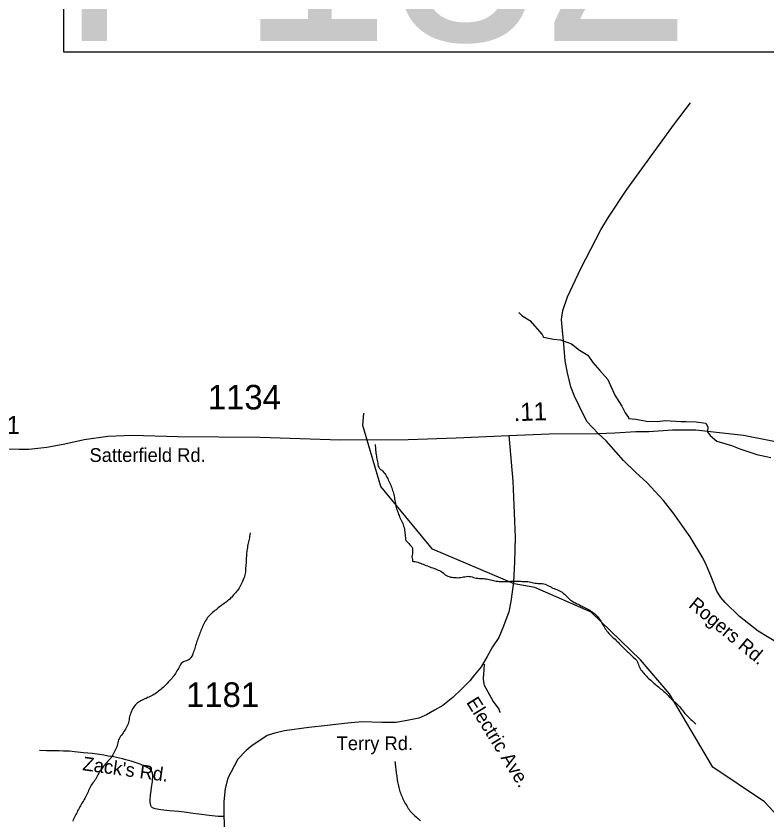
# Model space of a CAD drawing. Extents: x 1950930 to 2061844, y 904556 to 1017002.
# Drawn here: x 1990305 to 1995505, y 917098 to 922665 of the extents above; entities that cross this region are included whole.
import ezdxf

# ---------------------------------------------------------------- set-up
doc = ezdxf.new("R2010")
doc.units = 0
for name, color, linetype in [('Exist Hydrographic Creek Single Shore', 7, 'Continuous'), ('Exist Hydrographic Misc Water Feature', 7, 'Continuous'), ('Exist Road Non-System Type 51', 7, 'Continuous'), ('Exist Road Non-System Type 51 Label', 7, 'Continuous'), ('Exist Road Primary US Structure Standard Bridge CELL', 7, 'Continuous'), ('Exist Road Secondary Structure Pipe Number Label', 7, 'Continuous'), ('Exist Road Secondary Type 41 Attributed', 7, 'Continuous'), ('Exist Road Secondary Type 51 Attributed', 7, 'Continuous'), ('Exist Road Secondary Type 51 Label', 7, 'Continuous'), ('Exist Road Secondary Type 51 Number Label', 7, 'Continuous')]:
    doc.layers.add(name, color=color, linetype=linetype)

msp = doc.modelspace()

# ---------------------------------------------------------------- linework, layer by layer
at = {"layer": 'Exist Hydrographic Creek Single Shore'}
msp.add_lwpolyline([(1992928.9, 917501.3), (1992930.3, 917491.4), (1992931.1, 917481.6), (1992932.4, 917470.8), (1992932.8, 917460.9), (1992934.2, 917451), (1992935, 917441.2), (1992936.5, 917431.2), (1992938.1, 917421.2), (1992939.5, 917411.6), (1992940.8, 917401.7), (1992942.6, 917391.7), (1992943.8, 917381.8), (1992945.3, 917372.3), (1992946.9, 917362.2), (1992948.4, 917352.3), (1992950.4, 917342.2), (1992952.3, 917332.6), (1992954.9, 917322.4), (1992957, 917312.8), (1992960.3, 917303.8), (1992963.1, 917293.6), (1992966.8, 917284.5), (1992970.3, 917275.5), (1992974, 917266.5), (1992978.3, 917256.4), (1992982.2, 917247.3), (1992986.7, 917238.1), (1992990.8, 917230.2), (1992995.7, 917220.9), (1993000.4, 917211.6), (1993005.4, 917202.8), (1993010.7, 917194.3), (1993015.8, 917186.2), (1993021.2, 917177.7), (1993026.7, 917169.6), (1993032.4, 917161), (1993038.8, 917153.5), (1993045.3, 917146), (1993052.1, 917139.2), (1993059.9, 917132.4), (1993067.5, 917126), (1993075.3, 917119.1), (1993083.5, 917112.6), (1993090.9, 917105.8), (1993098.7, 917098.9), (1993105.6, 917092.2)], dxfattribs=at)
at = {"layer": 'Exist Hydrographic Misc Water Feature'}
for points in [[(1993786.8, 920611.9), (1993807.3, 920590.1), (1993861.7, 920556.3), (1993948.4, 920459.1), (1993958.4, 920441), (1994026.5, 920428.2), (1994074.7, 920422), (1994151, 920395), (1994207, 920351.3), (1994263.6, 920315.8), (1994300.1, 920266.5), (1994346.4, 920209.1), (1994403, 920147.3), (1994452, 920039.2), (1994500.2, 919963.7), (1994522.7, 919918.1), (1994545.3, 919884.3), (1994545.5, 919878.1), (1994597.2, 919872.3), (1994671.6, 919859.3), (1994745.4, 919856.3), (1994803.3, 919864.9), (1994909.3, 919857.7), (1994943.7, 919857.8), (1995015.3, 919854.5), (1995081.5, 919846.5), (1995095.7, 919820.9), (1995093.8, 919785), (1995112.1, 919759.1), (1995156.6, 919719.9), (1995258.7, 919690.6), (1995317.1, 919668.6), (1995435.6, 919627.5), (1995531.6, 919606.8)], [(1995753.4, 915179.5), (1995761.3, 915297.4), (1995645.3, 915496.7), (1995470.4, 915730), (1995395.3, 915872.8), (1995245.2, 916036.6), (1995270.2, 916170.7), (1995629.3, 916639.2), (1995654.3, 916720.7), (1995579.2, 917122.6), (1995488.2, 917223), (1995129.4, 917463.3), (1994830.2, 917971.6), (1994630.2, 918205.5), (1994288.2, 918537.4), (1993897.2, 918706.3), (1993755.3, 918732.1), (1993189.1, 918973.6), (1992830.3, 919407.6), (1992706.2, 919830.2), (1992714.2, 919915.4)], [(1992791.3, 919697.1), (1992792.1, 919687.2), (1992793.5, 919677.3), (1992794, 919667.5), (1992795, 919657.6), (1992795.8, 919647.7), (1992797, 919637), (1992798.3, 919627), (1992800.1, 919617.5), (1992802, 919608.3), (1992804.2, 919598.2), (1992806.3, 919588.5), (1992808.1, 919578.5), (1992809.3, 919568.6), (1992810.2, 919557.9), (1992811.6, 919548.4), (1992816.1, 919540), (1992822, 919532.5), (1992829.4, 919524.9), (1992837.2, 919518.9), (1992845, 919512), (1992852.4, 919504.8), (1992858.8, 919496.9), (1992864.1, 919488.8), (1992869, 919480.3), (1992873.5, 919471.6), (1992878.4, 919462.3), (1992882.9, 919453.8), (1992887.3, 919443.9), (1992891.4, 919435.2), (1992895.3, 919425.7), (1992899.4, 919416.9), (1992902.8, 919407.4), (1992906.3, 919397.6), (1992909.4, 919388.5), (1992912.9, 919378.7), (1992916.2, 919369.7), (1992918.6, 919359.6), (1992920.9, 919350.7), (1992923.1, 919340.7), (1992925.4, 919330.9), (1992926.6, 919321), (1992928.9, 919310.9), (1992930.1, 919301), (1992932.4, 919291.3), (1992933.6, 919281.4), (1992935.9, 919271.8), (1992938.1, 919261.7), (1992940.6, 919252), (1992943.2, 919242.6), (1992946.3, 919232.8), (1992950, 919223.8), (1992953.5, 919213.8), (1992957, 919204.8), (1992960.7, 919195.7), (1992964.6, 919186.6), (1992969.5, 919177.3), (1992973.4, 919168.2), (1992978.3, 919159), (1992982.4, 919150.3), (1992985.9, 919140.7), (1992989, 919131.7), (1992991.6, 919122.1), (1992994.3, 919111.9), (1992995.9, 919102.3), (1992997.4, 919092.3), (1992998.2, 919082.5), (1992999.6, 919072.6), (1993000, 919062.7), (1993000.9, 919052.9), (1993000.9, 919042.3), (1993005, 919033.2), (1993011.3, 919025.3), (1993018.3, 919018.9), (1993025, 919011.4), (1993031.8, 919003.9), (1993039.6, 918996.3), (1993046, 918988.8), (1993050.1, 918980.5), (1993049.7, 918969.9), (1993049.7, 918959.8), (1993049.7, 918950), (1993049.9, 918940.3), (1993048, 918930.5), (1993045.6, 918920.6), (1993047.4, 918910.7), (1993050.1, 918900.9), (1993050.3, 918890.3), (1993057.9, 918886.8), (1993068.7, 918887.9), (1993078.2, 918885.6), (1993087.2, 918882.3), (1993096.4, 918878.5), (1993106, 918875), (1993115.7, 918871.4), (1993124.9, 918868), (1993134.3, 918863.7), (1993143.6, 918860.3), (1993153.2, 918856.8), (1993162.4, 918853.4)], [(1991926, 919086.4), (1991923.9, 919071.6), (1991922.7, 919062.1), (1991921, 919052.3), (1991919.4, 919042.3), (1991917.4, 919032.5), (1991914.5, 919022.8), (1991911.6, 919013.9), (1991909.6, 919004.1), (1991908.3, 918994.1), (1991907.1, 918983.4), (1991905.5, 918973.8), (1991904.2, 918963.9), (1991903, 918953.9), (1991901.8, 918944.4), (1991901.4, 918934.2), (1991900.3, 918924.7), (1991899.7, 918913.8), (1991898.9, 918904.2), (1991898.5, 918894.2), (1991897.9, 918884.5), (1991897.5, 918874.4), (1991896, 918864), (1991895.6, 918854), (1991895, 918844.3), (1991894.6, 918834.3), (1991894, 918823.8), (1991892.8, 918813.9), (1991891.7, 918804.2), (1991890.1, 918794.4), (1991887, 918784.7), (1991883.9, 918775.4), (1991880.2, 918766.6), (1991876.6, 918756.7), (1991872.5, 918748), (1991867.9, 918738.8), (1991863.6, 918730.2), (1991859.1, 918721.2), (1991854.2, 918712.2), (1991849.3, 918703.2), (1991843.9, 918694.2), (1991838.4, 918686.5), (1991832.1, 918679), (1991825.7, 918671.1), (1991818.9, 918664), (1991811.8, 918656.5), (1991805.4, 918648.6), (1991798.6, 918641), (1991791.7, 918634.9), (1991784.5, 918627.4), (1991777.3, 918620.3), (1991769.7, 918613.8), (1991761.9, 918607.3), (1991754.1, 918601.1), (1991745.9, 918595.5), (1991737.7, 918589.9), (1991729.5, 918584.2), (1991721.3, 918578.2), (1991713.5, 918572.4), (1991705.3, 918566), (1991698, 918559.4), (1991690, 918553.3), (1991682.2, 918546.8), (1991674.2, 918540.2), (1991666.4, 918533.8), (1991659.4, 918527.5), (1991651.4, 918520.1), (1991644.8, 918513.9), (1991638.1, 918506.8), (1991631.5, 918498.4), (1991626, 918490.3), (1991620.9, 918482.2), (1991615.5, 918473.7), (1991610.6, 918464.7), (1991605.9, 918455.7), (1991601, 918446.7), (1991596.9, 918437.6), (1991592.8, 918428.9), (1991588.7, 918419.8), (1991585.4, 918410), (1991581.5, 918401.3), (1991578, 918391.3), (1991574.5, 918382.6), (1991570.6, 918372.5), (1991567.5, 918363.7), (1991564.3, 918354.1), (1991560.6, 918344.8), (1991557.7, 918335.2), (1991554.4, 918325.6), (1991551.5, 918316.6), (1991548.7, 918306.5), (1991546.2, 918296.7), (1991543.3, 918287), (1991539.9, 918277.4), (1991537.2, 918268.4), (1991533.9, 918258.4), (1991530.2, 918249.7), (1991526.5, 918239.6), (1991521.6, 918231), (1991516.3, 918222.1)], [(1993162.4, 918853.4), (1993171.5, 918850), (1993180.7, 918846.5), (1993190.3, 918843), (1993200, 918839.5), (1993209.6, 918836), (1993218.8, 918832.6), (1993227.8, 918828.4), (1993237.1, 918824.5), (1993245.7, 918820.4), (1993254.5, 918815.4), (1993262.5, 918809.8), (1993270.3, 918802.9), (1993277.7, 918796), (1993286.1, 918790.7), (1993295.3, 918786.5), (1993304.3, 918782.3), (1993314.6, 918779.5), (1993324.4, 918778), (1993334.1, 918777), (1993344.1, 918775.8), (1993353.7, 918775.6), (1993364, 918775.2), (1993374.3, 918776.2), (1993384.1, 918776.7), (1993394.1, 918778), (1993404, 918780.6), (1993413.8, 918781.9), (1993424.1, 918783.9), (1993433.5, 918784.6), (1993443.2, 918783.5), (1993453, 918782.4), (1993462.8, 918780.2), (1993472.7, 918777.4), (1993481.9, 918774.8), (1993492.2, 918772.1), (1993502.2, 918770.9), (1993512.3, 918769.8), (1993522.1, 918770.3), (1993531.7, 918770.4), (1993542, 918770.1), (1993551.8, 918768.3), (1993561.7, 918766.3), (1993571.5, 918764.4), (1993581.2, 918762.5), (1993590.8, 918760.3), (1993601.2, 918758.3), (1993610.5, 918755.6), (1993620.3, 918753.7), (1993630.4, 918751.9), (1993640.2, 918750.7), (1993649.8, 918749.7), (1993660.1, 918749.7), (1993670.1, 918748.6), (1993680, 918749.2), (1993689.6, 918748.9), (1993700.1, 918749.7), (1993709.7, 918749.5), (1993720, 918749.9), (1993729.8, 918750.5), (1993740.1, 918750.5), (1993749.9, 918751), (1993760.2, 918750.7), (1993769.8, 918750.5), (1993780.1, 918750.5), (1993789.9, 918751.1), (1993800.6, 918750.7), (1993810, 918749.7), (1993820.2, 918749.7), (1993830.5, 918749.4), (1993840.1, 918748.4), (1993849.8, 918748.1), (1993859.6, 918746.2), (1993870.1, 918744.6), (1993879.9, 918742.7), (1993889.1, 918740.1), (1993899.2, 918738.1), (1993909, 918737), (1993919.1, 918736), (1993929.3, 918736), (1993939, 918734.9), (1993949, 918733.8), (1993958.9, 918731.9), (1993968.5, 918729.2), (1993977.7, 918725), (1993987.4, 918721.5), (1993996.4, 918717.3), (1994005, 918713.1), (1994013.4, 918707.8), (1994023, 918703.5), (1994031.7, 918700.2), (1994041.3, 918695.9), (1994050.9, 918692.4), (1994059.9, 918688.9), (1994069, 918684.3), (1994078, 918679.3), (1994086.2, 918674.4), (1994094, 918668.4), (1994101.8, 918661.8), (1994109.2, 918655.1)], [(1994109.2, 918655.1), (1994116.1, 918647.6), (1994123.3, 918640.7), (1994130.3, 918633.2), (1994137, 918625.6), (1994144.6, 918620.1), (1994153, 918614.8), (1994161.7, 918609.8), (1994170.5, 918604.4), (1994179.1, 918600.2), (1994188.1, 918595.2), (1994197.1, 918591), (1994206.1, 918586.8), (1994215, 918581.4), (1994224.2, 918577.1), (1994233.2, 918572.9), (1994241.8, 918567.9), (1994250.6, 918563.3), (1994259.9, 918559.1), (1994268.3, 918554.2), (1994277.3, 918549.6), (1994285.7, 918543.8), (1994294.3, 918538.9), (1994302.5, 918532.8), (1994310.9, 918527), (1994318.5, 918521), (1994325.3, 918513.5), (1994331.6, 918506), (1994337.6, 918497.8), (1994343.5, 918490), (1994348.9, 918481.9), (1994354.2, 918473), (1994359.5, 918464.5), (1994364.7, 918456), (1994369.8, 918447), (1994374.9, 918438.5), (1994380.2, 918430.4), (1994385.6, 918421.1), (1994390.9, 918413), (1994397.1, 918405.6), (1994403.2, 918396.9), (1994409.2, 918389.5), (1994415.9, 918382), (1994423.5, 918375.6), (1994430.9, 918368.8), (1994438.1, 918361.9), (1994445.4, 918355.2), (1994452.8, 918348.4), (1994460.2, 918340.8), (1994467.6, 918334.4), (1994474.6, 918327.6), (1994481.7, 918320), (1994489.1, 918313.2), (1994496.1, 918306.5), (1994502.9, 918299), (1994509.8, 918292.2), (1994517, 918284.6), (1994523.8, 918277.2), (1994530.7, 918270.4), (1994538.1, 918262.8), (1994545.1, 918256), (1994551.9, 918249), (1994559.2, 918242.1), (1994566.6, 918235.3), (1994574, 918228.6), (1994581.8, 918222), (1994589.6, 918215.2), (1994596.6, 918208.5), (1994602.9, 918201), (1994607.8, 918192.5), (1994611.5, 918183.4), (1994615, 918173.6), (1994618.1, 918163.8), (1994621.6, 918154.7), (1994626.5, 918146.2), (1994632.5, 918138), (1994638.4, 918130.2), (1994644.6, 918122), (1994651.1, 918114.6), (1994657.9, 918107), (1994664.2, 918099.6), (1994671.4, 918092), (1994678.4, 918084.4), (1994685.4, 918077.6), (1994692.3, 918071.3), (1994700.1, 918064.5), (1994707.5, 918057.6), (1994714.9, 918050.9), (1994722.3, 918044.4), (1994730.1, 918037.6), (1994737.4, 918030.8), (1994745.4, 918025.1), (1994753, 918018.3), (1994761, 918012.2), (1994768.4, 918005.8), (1994776.4, 917999.7), (1994784.2, 917992.9), (1994791.6, 917986.8), (1994799.2, 917980.4), (1994806.3, 917972.9)], [(1991516.3, 918222.1), (1991510.7, 918214.1), (1991503.4, 918208.3), (1991494.1, 918204.4), (1991484.5, 918199.8), (1991475.5, 918195.9), (1991465.4, 918192.6), (1991456.6, 918187.8), (1991449.6, 918181.5), (1991443.7, 918174.3), (1991439.2, 918164.5), (1991434.7, 918155.5), (1991429.7, 918146.8), (1991424.6, 918138.6), (1991419.3, 918129.7), (1991414, 918120.8), (1991408.8, 918112.7), (1991403.5, 918103.8), (1991398, 918095.7), (1991391.8, 918087.7), (1991385.9, 918079.6), (1991379.1, 918072.1), (1991372.7, 918064.9), (1991365.8, 918058), (1991359, 918050.5), (1991351.8, 918043.4), (1991344.6, 918036), (1991337.5, 918028.5), (1991330.5, 918022.3), (1991322.9, 918015.3), (1991315.5, 918008.7), (1991307.7, 918001.4), (1991299.9, 917995.3), (1991292.6, 917988.8), (1991284.4, 917983), (1991277, 917976.9), (1991268.4, 917971.3), (1991260, 917966.5), (1991251.3, 917960.9), (1991242.5, 917957), (1991233.3, 917952.3), (1991224.7, 917948.4), (1991215.1, 917944.5), (1991205.6, 917939.4), (1991196.6, 917936), (1991187.4, 917931.6), (1991178.1, 917926.9), (1991169.7, 917922.1), (1991161.3, 917917.8), (1991152.7, 917912.2), (1991144.9, 917905.6), (1991136.9, 917899.1), (1991129.8, 917892.1), (1991123.8, 917883.7), (1991117.7, 917875.7), (1991112.5, 917867.6), (1991108.2, 917858.9), (1991104.1, 917849.7), (1991100, 917840.2), (1991096.7, 917831), (1991093.5, 917821.3), (1991091, 917811.6), (1991089.4, 917801.6), (1991087.7, 917791.8), (1991086.5, 917782.3), (1991084.4, 917772.4), (1991081.4, 917762.3), (1991077.5, 917753.6), (1991073, 917744.5), (1991068, 917735.9), (1991062.7, 917727), (1991057.6, 917718.8), (1991052.2, 917709.9), (1991046.7, 917701.8), (1991041.2, 917693.8), (1991035, 917685.4), (1991029.3, 917676.5), (1991023.7, 917668.8), (1991018.8, 917659.4), (1991014.5, 917651.5), (1991011.2, 917641.9), (1991009.6, 917632), (1991007.5, 917622.1), (1991005.5, 917612.3), (1991002.6, 917602.6), (1990998.5, 917593.5), (1990994, 917584.4), (1990989.5, 917575.8), (1990984.8, 917566.8), (1990979.9, 917557.7), (1990974.9, 917548.8), (1990969.8, 917540.6), (1990964.1, 917531.8), (1990958.7, 917523.6), (1990952.8, 917516), (1990946.4, 917508.4), (1990939.5, 917501.4), (1990932.3, 917494), (1990925.1, 917487), (1990918.8, 917479.4)], [(1994806.3, 917972.9), (1994813.3, 917966.1), (1994819.7, 917958.6), (1994826.8, 917951), (1994833.8, 917944.3), (1994840.6, 917936.8), (1994848, 917930), (1994855.3, 917923.1), (1994863.3, 917916.7), (1994871.1, 917909.8), (1994878.1, 917904.3), (1994885.5, 917897.5), (1994892.9, 917889.9), (1994899.6, 917882.3), (1994906, 917874.8), (1994911.5, 917867.2), (1994917.9, 917858.9), (1994924, 917850.6), (1994930, 917843.3), (1994936.3, 917835.4), (1994943.3, 917827.9), (1994950.1, 917820.3), (1994957.1, 917813.5), (1994964.2, 917806.4), (1994971.2, 917799.6), (1994978.2, 917792.9), (1994985.8, 917785.2), (1994992.7, 917778.5), (1995000.7, 917772), (1995012, 917760.9)], [(1990918.8, 917479.4), (1990912.2, 917471.4), (1990906.2, 917463.4), (1990900.7, 917455.3), (1990894.4, 917447.4), (1990888.6, 917438.9), (1990883.1, 917430.8), (1990877.7, 917421.9), (1990873.4, 917414.1), (1990868.7, 917404.3), (1990864.8, 917395.4), (1990860.3, 917386.4), (1990855.2, 917378.3), (1990849.4, 917369.4), (1990843.1, 917362.2), (1990837.1, 917354.2), (1990831, 917345.8), (1990825.7, 917337.3), (1990820.9, 917329.1), (1990816.4, 917320), (1990812.5, 917311), (1990807.8, 917301.4), (1990803.7, 917292.3), (1990799.8, 917283.6), (1990795.7, 917274.5), (1990791.6, 917264.6), (1990787.1, 917255.9), (1990782.2, 917246.9), (1990777.9, 917238.7), (1990772.1, 917229.8), (1990767, 917221.7), (1990761.7, 917212.7), (1990756.1, 917204.6), (1990751.2, 917195.6), (1990746.1, 917187.9), (1990741.2, 917178.9), (1990736.7, 917169.9), (1990731.7, 917160.9), (1990727.4, 917152.1), (1990722.9, 917143.1), (1990718.4, 917134.1), (1990713.9, 917125.4), (1990709.8, 917116.3), (1990705.9, 917107.1), (1990701.6, 917097.6), (1990698.1, 917088.5)]]:
    msp.add_lwpolyline(points, dxfattribs=at)
at = {"layer": 'Exist Road Non-System Type 51'}
for points in [[(1993545.6, 918176.1), (1993544.9, 918139.6), (1993541.5, 918101.9), (1993539.5, 918086.4), (1993540.1, 918071.6), (1993543.5, 918039.2), (1993547.5, 918031.2), (1993557.6, 918009.6), (1993609.5, 917917.4), (1993647.9, 917863.5), (1993653.9, 917848), (1993656.6, 917840.6)], [(1991745.2, 917121.1), (1991704.4, 917120.8), (1991643.4, 917127.9), (1991570.8, 917138.4), (1991531.2, 917142.9), (1991468.8, 917150.8), (1991431.5, 917155.1), (1991367, 917161), (1991307, 917168.2), (1991267.6, 917173.2), (1991250.6, 917180.8), (1991242.8, 917188.6), (1991237.6, 917197.1), (1991235, 917208.1), (1991233.6, 917221.5), (1991234, 917237.1), (1991236.9, 917268.4), (1991246.4, 917334.8), (1991249, 917364.1), (1991251.6, 917404.4), (1991249.6, 917421.3), (1991244.1, 917437.6), (1991235, 917447.1), (1991226.1, 917454.6), (1991200.1, 917468.2), (1991165.2, 917482.9), (1991129, 917495.4), (1991101.4, 917505.2), (1991066.1, 917514.7), (1991041.6, 917520.2), (1990979.1, 917533.8), (1990942.6, 917540.2), (1990912, 917546.8), (1990882.2, 917550.9), (1990832.4, 917557.4), (1990772.5, 917563.2), (1990710.1, 917569.4), (1990676, 917572.9), (1990633.6, 917574.8), (1990604.2, 917576.4), (1990546.2, 917575.8), (1990515.6, 917575.1), (1990468, 917578.4)]]:
    msp.add_lwpolyline(points, dxfattribs=at)
at = {"layer": 'Exist Road Secondary Structure Pipe Number Label'}
msp.add_lwpolyline([(1990634.9, 923949.2), (1995699.4, 923949.2), (1995699.4, 922413.8), (1990634.9, 922413.8)], close=True, dxfattribs=at)
at = {"layer": 'Exist Road Secondary Type 41 Attributed'}
msp.add_lwpolyline([(1994336.6, 919774.2), (1994256.4, 919857.7), (1994204.7, 919965.9), (1994172.8, 920032), (1994147.1, 920096), (1994123.3, 920194.2), (1994107.5, 920276.2), (1994097.7, 920392.2), (1994088, 920486.2), (1994082.1, 920564.2), (1994090.2, 920626), (1994122.5, 920720.1), (1994215, 920915.8), (1994355.5, 921185.3), (1994407.7, 921271.2), (1994534.2, 921462.9), (1994865.1, 921918.1), (1994976.2, 922063.2)], dxfattribs=at)
at = {"layer": 'Exist Road Secondary Type 51 Attributed'}
for points in [[(1994336.6, 919774.2), (1994450.5, 919779.4), (1994597.7, 919787.8), (1994687.6, 919787.4), (1994850.4, 919798.4), (1995011.8, 919799.1), (1995154.3, 919783.6), (1995342.1, 919761.2), (1995682, 919696.4), (1995996.2, 919651), (1996240.6, 919619.9), (1996604.1, 919557.8), (1996765.7, 919533.9), (1997027.7, 919493.5), (1997283.5, 919448), (1997674.5, 919385.8), (1997839.2, 919359.9), (1998078.9, 919321.6), (1998461.6, 919260.5), (1998959.7, 919182.9)], [(1990223.8, 919667.2), (1990327.8, 919664.9), (1990394.6, 919666.4), (1990517.6, 919680.1), (1990643.6, 919702.9), (1990775.7, 919733.3), (1990939.6, 919756), (1991109.2, 919761.9), (1991425.2, 919753.4), (1991996.3, 919748.5), (1992550.3, 919731), (1993019.6, 919733.3), (1993352.1, 919743.9), (1993717.3, 919759.8)], [(1993717.3, 919759.8), (1993744, 919442.6), (1993762, 919056.7), (1993756.9, 918884.2), (1993750.8, 918744.4), (1993731.4, 918610.5), (1993717.8, 918538.4), (1993681, 918438.9), (1993647.6, 918361.4), (1993605.3, 918296.6), (1993567.7, 918228.4), (1993526.2, 918158.1), (1993480.5, 918102), (1993446.6, 918061.8), (1993392.9, 918005.5), (1993329.2, 917945.3), (1993259.6, 917890.8), (1993201.8, 917856.6), (1993147.9, 917824.5), (1993094.2, 917802.1), (1993024.2, 917787.8), (1992936.3, 917771.4), (1992839.1, 917771.1), (1992702.5, 917777.2), (1992600.7, 917766.5), (1992459.5, 917751.3), (1992332, 917737.6), (1992163.5, 917714.9), (1992096.7, 917698.1), (1992043.5, 917682.9), (1991993.1, 917648.7), (1991939.4, 917612.5), (1991899.6, 917578.4), (1991839.9, 917518), (1991770.5, 917387.7), (1991754.3, 917314.5), (1991743.7, 917224.8), (1991742.9, 917149.6), (1991746, 917049.3)], [(1993717.3, 919759.8), (1993997.4, 919771.2), (1994336.6, 919774.2)], [(1995597, 918311.9), (1995443.2, 918404.3), (1995315.4, 918506.5), (1995215.2, 918602.3), (1995186.3, 918638.7), (1995157.5, 918681.3), (1995117.1, 918788.7), (1995086.7, 918860.6), (1995060.5, 918912.5), (1994973, 919058.6), (1994854.8, 919223.3), (1994789.2, 919310.2), (1994730, 919372.6), (1994675.7, 919432.5), (1994593.4, 919506.1), (1994510.9, 919587.5), (1994390.4, 919722.4), (1994336.6, 919774.2)]]:
    msp.add_lwpolyline(points, dxfattribs=at)

# ---------------------------------------------------------------- texts
at = {"layer": 'Exist Road Non-System Type 51 Label'}
for s, rotation, p in [('Electric Ave.', 301.8142, (1993420.1, 917912.2)), ("Zack's Rd.", 352.1814, (1990761.8, 917442.3))]:
    msp.add_text(s, height=95, rotation=rotation, dxfattribs=at).set_placement(p)
at = {"layer": 'Exist Road Primary US Structure Standard Bridge CELL'}
for s, rotation, p in [('.11', 1.9367, (1993751.4, 919858.6)), ('1.31', 358.7445, (1990005.9, 919776.6))]:
    msp.add_text(s, height=125, rotation=rotation, dxfattribs=at).set_placement(p)
at = {"layer": 'Exist Road Secondary Structure Pipe Number Label'}
msp.add_text('P132', height=1400, dxfattribs=at).set_placement((1990606.4, 922492.9))
at = {"layer": 'Exist Road Secondary Type 51 Label'}
for s, p in [('Satterfield Rd.', (1990813.5, 919577.1)), ('Terry Rd.', (1992524.9, 917580.8))]:
    msp.add_text(s, height=95, dxfattribs=at).set_placement(p)
msp.add_text('Rogers Rd.', height=95, rotation=320.28, dxfattribs=at).set_placement((1994955.8, 918576))
at = {"layer": 'Exist Road Secondary Type 51 Number Label'}
for s, p in [('1134', (1991633.4, 919940.4)), ('1181', (1991482.8, 917880))]:
    msp.add_text(s, height=170, dxfattribs=at).set_placement(p)

doc.saveas('drawing.dxf')
